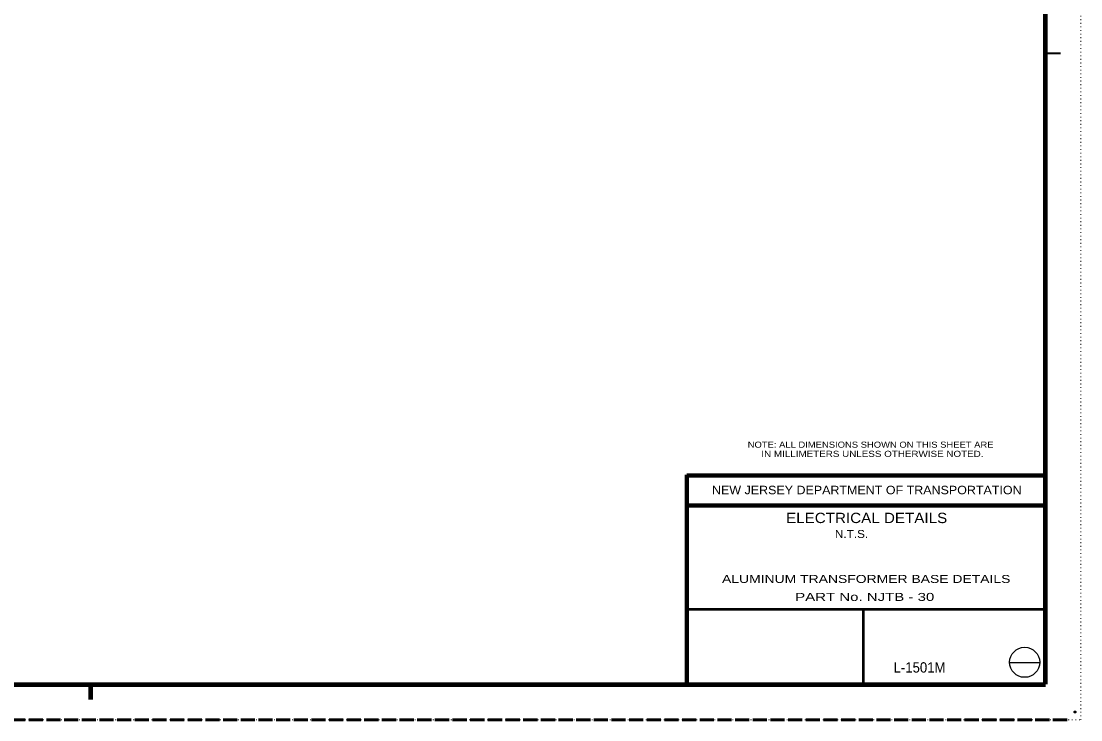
# Model space of a CAD drawing. Extents: x 312583 to 312854, y 144419 to 144597.
# Drawn here: x 312718.5 to 312853.5, y 144418.6 to 144507.7 of the extents above; entities that cross this region are included whole.
import ezdxf
from ezdxf.enums import TextEntityAlignment as Align

# ---------------------------------------------------------------- set-up
doc = ezdxf.new("R2010")
doc.units = 0
doc.header["$LTSCALE"] = 0.3
doc.header["$PDMODE"] = 32
doc.header["$PDSIZE"] = 0.15
doc.linetypes.add('DOTTED', pattern=[1.5, 0.3, -1.2])
doc.linetypes.add('LONG_DASHED', pattern=[7.5, 6, -1.5])
for name, color, linetype, lineweight in [('1', 7, 'Continuous', 40), ('10', 7, 'Continuous', 25), ('2', 7, 'Continuous', 13), ('63', 7, 'DOTTED', 13)]:
    doc.layers.add(name, color=color, linetype=linetype, lineweight=lineweight)

msp = doc.modelspace()

# ---------------------------------------------------------------- linework, layer by layer
at = {"layer": '1', "lineweight": 158}
for p, q in [((312849, 144423.1446), (312849, 144585.0846)), ((312616.5, 144423.0846), (312849, 144423.0846)), ((312727.35, 144421.1646), (312727.35, 144423.0846))]:
    msp.add_line(p, q, dxfattribs=at)
at = {"layer": '1', "lineweight": 35}
msp.add_line((312849, 144503.6216), (312850.932, 144503.6216), dxfattribs=at)
at = {"layer": '1', "lineweight": 80}
for p, q in [((312803.31, 144423.1446), (312803.31, 144449.8146)), ((312803.31, 144449.7246), (312849, 144449.7246)), ((312803.31, 144445.9146), (312849, 144445.9146))]:
    msp.add_line(p, q, dxfattribs=at)
at = {"layer": '1', "lineweight": 53}
for p, q in [((312849, 144432.6666), (312803.1456, 144432.6666)), ((312825.7546, 144432.6666), (312825.7546, 144423.1446))]:
    msp.add_line(p, q, dxfattribs=at)
at = {"layer": '1', "linetype": 'LONG_DASHED', "lineweight": 60}
msp.add_line((312851.75, 144418.5846), (312583.526, 144418.5846), dxfattribs=at)
at = {"layer": '1'}
msp.add_point((312852.75, 144419.5846), dxfattribs=at)
at = {"layer": '10'}
msp.add_line((312844.4383, 144425.9059), (312848.2793, 144425.9059), dxfattribs=at)
msp.add_circle((312846.3494, 144425.9205), 1.9159, dxfattribs=at)
at = {"layer": '63'}
msp.add_lwpolyline([(312601.2, 144418.5846), (312853.5, 144418.5846), (312853.5, 144596.7846)], dxfattribs=at)

# ---------------------------------------------------------------- texts
at = {"layer": '1'}
for s, width, p in [('NOTE: ALL DIMENSIONS SHOWN ON THIS SHEET ARE', 1.15, (312811.0528, 144453.2864)), ('     IN MILLIMETERS UNLESS OTHERWISE NOTED.', 1.2, (312811.0527, 144452.1164))]:
    msp.add_text(s, height=0.78, dxfattribs=dict(at, width=width)).set_placement(p)
for s, height, width, p in [('NEW JERSEY DEPARTMENT OF TRANSPORTATION', 1.08, 1.1, (312826.2285, 144447.3546)), ('ELECTRICAL DETAILS', 1.315, 1.1, (312826.2107, 144443.676)), ('L-1501M', 1.319, 0.95, (312832.9484, 144424.609))]:
    msp.add_text(s, height=height, dxfattribs=dict(at, width=width)).set_placement(p, align=Align.CENTER)
at = {"layer": '2'}
for s, width, p in [('    N.T.S.  ', 1.1, (312823.87, 144441.778)), ('      ALUMINUM TRANSFORMER BASE DETAILS     ', 1.3, (312825.908, 144436.04)), ('             PART No. NJTB - 30             ', 1.4, (312825.9655, 144433.7476))]:
    msp.add_text(s, height=1.02, dxfattribs=dict(at, width=width)).set_placement(p, align=Align.CENTER)

doc.saveas('drawing.dxf')
